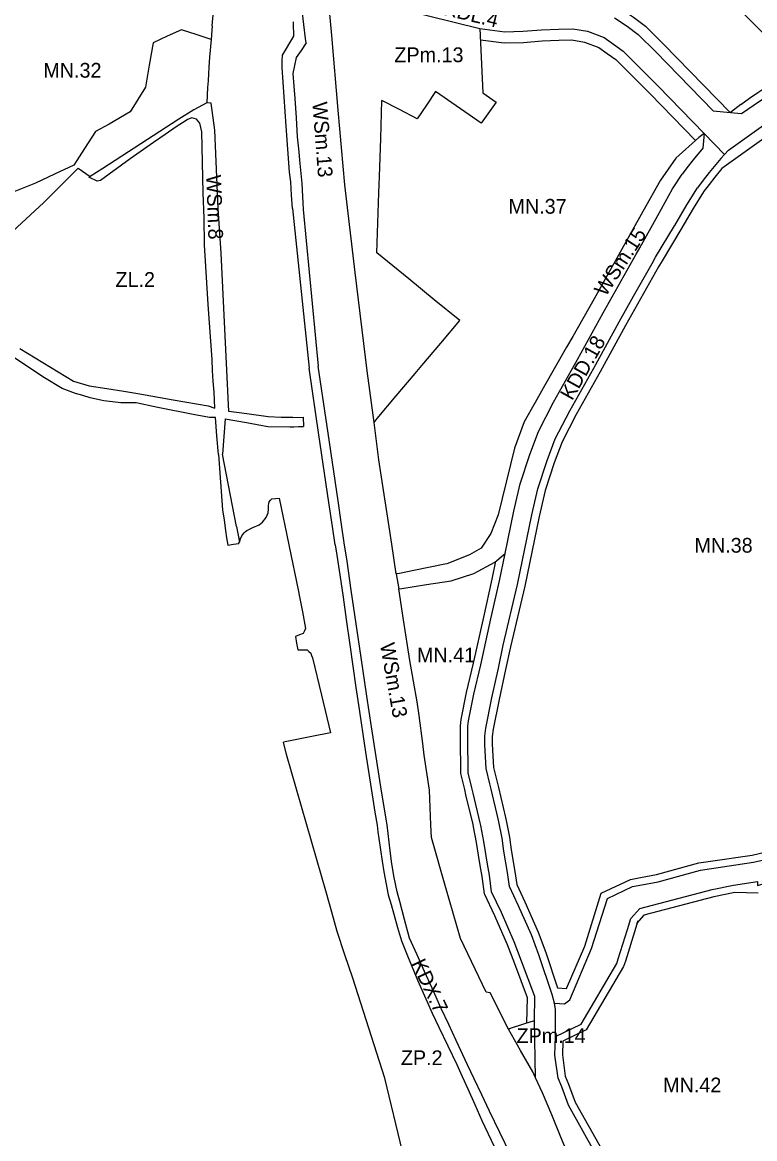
# Model space of a CAD drawing. Extents: x 7431080 to 7433370, y 5546450 to 5548428.
# Drawn here: x 7432562 to 7432959, y 5546903 to 5547508 of the extents above; entities that cross this region are included whole.
import ezdxf

# ---------------------------------------------------------------- set-up
doc = ezdxf.new("R2010")
doc.units = 0
for name, color, linetype in [('Linie Rozgraniczajace', 7, 'Continuous'), ('nieprzekraczalna linia zabudowy', 7, 'Continuous'), ('oznaczenia_przeznaczen', 7, 'Continuous')]:
    doc.layers.add(name, color=color, linetype=linetype)

msp = doc.modelspace()

# ---------------------------------------------------------------- linework, layer by layer
at = {"layer": 'Linie Rozgraniczajace'}
for p, q in [((7432665.2, 5547506.49), (7432664.53, 5547499.08)), ((7432709.13, 5547507.75), (7432709.11, 5547508.64)), ((7432709.31, 5547500.85), (7432709.13, 5547507.75)), ((7432883.07, 5547510.87), (7432889.86, 5547506.34)), ((7432889.86, 5547506.34), (7432895.91, 5547501.82)), ((7432895.91, 5547501.82), (7432905.46, 5547492.38)), ((7432592.52, 5547429.36), (7432599.07, 5547424.88)), ((7432708.89, 5547294.18), (7432714.49, 5547294.46)), ((7432714.49, 5547294.46), (7432714.64, 5547289.37)), ((7432822.84, 5547219.57), (7432823.82, 5547220.4)), ((7432764.79, 5547209.37), (7432766.17, 5547201.41))]:
    msp.add_line(p, q, dxfattribs=at)
for points in [[(7432684.27, 5547549.31), (7432684.63, 5547552.22), (7432685.71, 5547560.16), (7432692.57, 5547559.49), (7432702.74, 5547558.65), (7432706.07, 5547557.26), (7432714.86, 5547550.38), (7432718.05, 5547546.39), (7432720.97, 5547541.9), (7432726.36, 5547536.37), (7432730.08, 5547533.53), (7432738.98, 5547526.29), (7432754.14, 5547519.63), (7432768.49, 5547515.46), (7432810.21, 5547505.05)], [(7432665.2, 5547506.49), (7432665.75, 5547512.53), (7432667.77, 5547527.55), (7432669.79, 5547542.58)], [(7432774.33, 5547211.33), (7432766.65, 5547209.56), (7432764.79, 5547209.37), (7432762.43, 5547225.59), (7432755.48, 5547271.31), (7432752.81, 5547291.41), (7432749.09, 5547319.44), (7432742.62, 5547372.72), (7432736.91, 5547420.37), (7432733.47, 5547460.86), (7432730.03, 5547501.34), (7432727.43, 5547528.51), (7432726.36, 5547536.37)], [(7432928.37, 5547538.37), (7432936.78, 5547529.78), (7432945.54, 5547520.83), (7432954.3, 5547511.88), (7432958.8, 5547507.42), (7432963.3, 5547502.97), (7432972.96, 5547493.4), (7432982.62, 5547483.83)], [(7432716.06, 5547497.22), (7432715.66, 5547499.62), (7432714.76, 5547507.29), (7432713.86, 5547514.97)], [(7432640.78, 5547500.83), (7432633.11, 5547497.24), (7432631.07, 5547485.28), (7432629.04, 5547473.31), (7432624.91, 5547466.56), (7432620.78, 5547459.81), (7432609.32, 5547453.22), (7432601.93, 5547449.18), (7432596.03, 5547440.08), (7432590.13, 5547430.98), (7432579.76, 5547426.12), (7432569.39, 5547421.26), (7432543.12, 5547410.71), (7432516.84, 5547400.15), (7432508.77, 5547396.91), (7432500.7, 5547393.67), (7432500.07, 5547393.54), (7432492.82, 5547389.56), (7432485.57, 5547385.58), (7432484.07, 5547383.7), (7432482.57, 5547381.81)], [(7432664.53, 5547499.08), (7432656.52, 5547501.74), (7432648.45, 5547504.43), (7432640.78, 5547500.83)], [(7432708.67, 5547407.43), (7432708.19, 5547414.67), (7432707.71, 5547421.91), (7432707.05, 5547427.12), (7432706.17, 5547439.58), (7432705.29, 5547452.04), (7432704.14, 5547468), (7432702.99, 5547483.96), (7432703.12, 5547487.29), (7432703.24, 5547490.63), (7432709.31, 5547500.85)], [(7432810.21, 5547505.05), (7432811.69, 5547470.23), (7432818.94, 5547465.05), (7432810.8, 5547453.72), (7432786.16, 5547471.01)], [(7432810.21, 5547505.05), (7432823.61, 5547503.35), (7432833.51, 5547503.55)], [(7432833.51, 5547503.55), (7432843.54, 5547504.29), (7432852.74, 5547504.78), (7432860.43, 5547504.93), (7432868.49, 5547503.55), (7432877.4, 5547500.18), (7432882.61, 5547496.51), (7432887.79, 5547492.85), (7432897.26, 5547483.35), (7432906.72, 5547473.84), (7432931.58, 5547448.24), (7432942.68, 5547436.81)], [(7432664.53, 5547499.08), (7432663.67, 5547489.61), (7432663.35, 5547484.18), (7432663.13, 5547480.43), (7432662.92, 5547476.68), (7432662.57, 5547473.05), (7432662.28, 5547464.72)], [(7432716.06, 5547497.22), (7432713.27, 5547493.07), (7432710.71, 5547489.28), (7432709.78, 5547484.96), (7432708.85, 5547480.63), (7432709.41, 5547473.84), (7432709.96, 5547467.05), (7432710.59, 5547456.68), (7432711.22, 5547446.31), (7432712.03, 5547438.18), (7432712.49, 5547433.67), (7432713.75, 5547421.03), (7432714.11, 5547414.03), (7432714.29, 5547410.52)], [(7432905.46, 5547492.38), (7432936.53, 5547460.37), (7432945.96, 5547459.52), (7432951.94, 5547458.98)], [(7432951.44, 5547463.82), (7432956.27, 5547467.3), (7432960.65, 5547470.43), (7432962.98, 5547471.85), (7432972.8, 5547477.84), (7432982.62, 5547483.83)], [(7432786.16, 5547471.01), (7432781.15, 5547463.58), (7432776.15, 5547456.16), (7432766.64, 5547461.11), (7432757.13, 5547466.06)], [(7432708.89, 5547294.18), (7432704.88, 5547294.15), (7432702.53, 5547294.22), (7432695.5, 5547294.59), (7432683.88, 5547296.19), (7432674.21, 5547297.48), (7432670.08, 5547383.35), (7432668.43, 5547407.57), (7432666.58, 5547450), (7432664.66, 5547464.61), (7432662.41, 5547464.79), (7432662.28, 5547464.72), (7432655.28, 5547460.92), (7432647.01, 5547455.95), (7432605.86, 5547429.13), (7432599.07, 5547424.88), (7432598.33, 5547424.4)], [(7432752.81, 5547291.41), (7432754.6, 5547293.6), (7432764.87, 5547305.87), (7432775.14, 5547318.14), (7432778.69, 5547322.35), (7432788.98, 5547334.54), (7432799.27, 5547346.72), (7432785.46, 5547358.04), (7432771.65, 5547369.35), (7432762.95, 5547376.41), (7432754.25, 5547383.47), (7432754.85, 5547399.75), (7432755.45, 5547416.04), (7432755.6, 5547420.44), (7432755.75, 5547424.85), (7432756.44, 5547445.46), (7432757.13, 5547466.06)], [(7432951.44, 5547463.82), (7432945.96, 5547459.52)], [(7432951.94, 5547458.98), (7432958.79, 5547463.62), (7432965.39, 5547468.19)], [(7432560.85, 5547331.53), (7432585.82, 5547316.39), (7432590.09, 5547313.98), (7432598.54, 5547311.41), (7432608.02, 5547309.94), (7432617.34, 5547308.5), (7432624.88, 5547307.14), (7432644, 5547303.73), (7432663.03, 5547300.54), (7432666.51, 5547299.18), (7432666.19, 5547307.96), (7432665.72, 5547313.85), (7432665.25, 5547319.74), (7432665.05, 5547325.61), (7432663.03, 5547355.44), (7432661.04, 5547387.81), (7432660.75, 5547402.19), (7432660.18, 5547415.94), (7432659.57, 5547449.03), (7432658.53, 5547453.8), (7432656.7, 5547456.01), (7432654.09, 5547456.7), (7432651.79, 5547455.83), (7432650.95, 5547455.27), (7432645.71, 5547451.71), (7432639.73, 5547447.64), (7432633.41, 5547443.19), (7432620.69, 5547434.37)], [(7432944.76, 5547439.03), (7432965.08, 5547453.58), (7432971.88, 5547457.4)], [(7432931.58, 5547448.24), (7432928.7, 5547446.07), (7432916.31, 5547434.85), (7432908.06, 5547422.87), (7432898.49, 5547405.86), (7432872.15, 5547358.53), (7432860.44, 5547338.07)], [(7432931.58, 5547448.24), (7432931, 5547440.23), (7432925.7, 5547433.87), (7432922.36, 5547429.51), (7432919.79, 5547426.09)], [(7432620.69, 5547434.37), (7432604.64, 5547422.69), (7432602.9, 5547422.26), (7432598.33, 5547424.4)], [(7432944.76, 5547439.03), (7432942.68, 5547436.81), (7432940.62, 5547434.61), (7432934.3, 5547427), (7432931.12, 5547422.86), (7432927.99, 5547418.69)], [(7432592.52, 5547429.36), (7432583.24, 5547420.08), (7432573.95, 5547410.8), (7432528.05, 5547368.4), (7432529.17, 5547367.84), (7432530.29, 5547367.29), (7432525.74, 5547362.3), (7432521.19, 5547357.31)], [(7432820.79, 5547205.68), (7432823.82, 5547220.4), (7432828.6, 5547243.51), (7432831.96, 5547258.28), (7432837.16, 5547274.2), (7432841.86, 5547286.68), (7432850.06, 5547302.55), (7432863.11, 5547325.73), (7432876.88, 5547350.95), (7432894.75, 5547382.66), (7432896.75, 5547386.22), (7432906.53, 5547403.62), (7432914.57, 5547418.12), (7432919.79, 5547426.09)], [(7432830.58, 5547203.66), (7432838.37, 5547241.39), (7432841.61, 5547255.61), (7432846.6, 5547270.88), (7432851.01, 5547282.61), (7432858.86, 5547297.8), (7432871.86, 5547320.88), (7432885.62, 5547346.1), (7432893.47, 5547360.02), (7432903.46, 5547377.75), (7432905.39, 5547381.18), (7432915.61, 5547398.08), (7432915.65, 5547398.16), (7432915.7, 5547398.23), (7432922.34, 5547409.57), (7432927.99, 5547418.69)], [(7432714.29, 5547410.52), (7432714.47, 5547407.02), (7432722.59, 5547321.99)], [(7432708.67, 5547407.43), (7432717.66, 5547321.01)], [(7432663.63, 5547294.23), (7432654.79, 5547295.76), (7432635.74, 5547299.66), (7432623.93, 5547302.1), (7432615.72, 5547302.09), (7432611.11, 5547302.66), (7432606.5, 5547303.22), (7432598.99, 5547304.95), (7432595.07, 5547306.12), (7432591.15, 5547307.28), (7432583.92, 5547309.9), (7432574.27, 5547315.75), (7432553.87, 5547329.22), (7432541.98, 5547337.16), (7432533.37, 5547343.74), (7432530.34, 5547345.11)], [(7432860.44, 5547338.07), (7432857.12, 5547332.27), (7432844.46, 5547310.14), (7432840.05, 5547302.3), (7432834.15, 5547291.77), (7432828.9, 5547277.53), (7432820.11, 5547241.37), (7432816.15, 5547231.27), (7432810.77, 5547223.37), (7432804.57, 5547219.68), (7432792.19, 5547214.94), (7432791.24, 5547214.75), (7432774.33, 5547211.33)], [(7432731.77, 5547225.23), (7432730.29, 5547235.19), (7432728.38, 5547248.11), (7432723, 5547284.73), (7432717.66, 5547321.01)], [(7432736.7, 5547226.21), (7432735.22, 5547236.17), (7432733.31, 5547249.09), (7432727.92, 5547285.71), (7432722.59, 5547321.99)], [(7432668.54, 5547274.21), (7432667.74, 5547284.19), (7432666.93, 5547294.16), (7432663.63, 5547294.23)], [(7432672.22, 5547293.51), (7432671.44, 5547283.96), (7432670.66, 5547274.41)], [(7432672.22, 5547293.51), (7432683.76, 5547291.44), (7432695.29, 5547289.39), (7432707.2, 5547289.21), (7432709.29, 5547289.14)], [(7432709.29, 5547289.14), (7432711.96, 5547289.25), (7432714.64, 5547289.37)], [(7432668.54, 5547274.21), (7432669.64, 5547259.2), (7432670.74, 5547244.18), (7432671.54, 5547238.54), (7432672.35, 5547232.9), (7432672.96, 5547228.94), (7432673.58, 5547224.97), (7432676.61, 5547225.46), (7432679.64, 5547225.95), (7432679.61, 5547226.13), (7432679.86, 5547226.71), (7432680.54, 5547228.35), (7432681.23, 5547229.99), (7432681.82, 5547230.82), (7432682.41, 5547231.65), (7432683.12, 5547232.33), (7432683.84, 5547233.01), (7432687.21, 5547234.5), (7432690.57, 5547235.99), (7432692.46, 5547237.47), (7432694.38, 5547239.91), (7432694.95, 5547241.25), (7432695.52, 5547242.59), (7432695.62, 5547244.53), (7432695.72, 5547246.46), (7432695.9, 5547247.5), (7432696.07, 5547248.55), (7432696.74, 5547249.33), (7432697.4, 5547250.11), (7432699.45, 5547250.32), (7432701.5, 5547250.53), (7432706.71, 5547225.24), (7432711.92, 5547199.95), (7432712.34, 5547197.9), (7432714.02, 5547188.9), (7432715.7, 5547179.89), (7432715.11, 5547178.48), (7432714.51, 5547177.06), (7432712.37, 5547176.32), (7432710.23, 5547175.57), (7432710.84, 5547171.95), (7432711.45, 5547168.33), (7432714, 5547168.28), (7432716.54, 5547168.22), (7432717.53, 5547167.36), (7432718.52, 5547166.49), (7432719.01, 5547165.24), (7432719.5, 5547163.98), (7432724.33, 5547143.67), (7432729.17, 5547123.35), (7432719.19, 5547121.34), (7432709.21, 5547119.33), (7432706.53, 5547118.79), (7432703.85, 5547118.25)], [(7432678.25, 5547235.08), (7432670.66, 5547274.41)], [(7432678.25, 5547235.08), (7432679.86, 5547226.71)], [(7432731.77, 5547225.23), (7432732.65, 5547219.5), (7432734.25, 5547208.99), (7432736.02, 5547196.87), (7432737.78, 5547184.75), (7432739.74, 5547170.98), (7432743.03, 5547147.78), (7432744.35, 5547138.36), (7432748.23, 5547112.83), (7432752.1, 5547087.29), (7432753.28, 5547080.24), (7432754.46, 5547073.19), (7432754.96, 5547069.61), (7432755.46, 5547066.02), (7432756.3, 5547059.85), (7432757.15, 5547053.68), (7432758.21, 5547047.88), (7432760.52, 5547035.43), (7432762.01, 5547030.2), (7432763.5, 5547024.96), (7432765.57, 5547017.72), (7432767.63, 5547010.48), (7432770.96, 5547002.29), (7432776.51, 5546988.91), (7432781.54, 5546977.49), (7432784.35, 5546971.26), (7432787.92, 5546963.68), (7432797.66, 5546943.46), (7432800.62, 5546936.88), (7432803.59, 5546930.31), (7432807.44, 5546921.73), (7432811.29, 5546913.14), (7432817.81, 5546899.04)], [(7432826.52, 5546894.97), (7432820.99, 5546906.58), (7432815.45, 5546918.19), (7432811.29, 5546926.96), (7432807.13, 5546935.74), (7432805.32, 5546939.55), (7432803.51, 5546943.37), (7432797.38, 5546956.42), (7432793.32, 5546965.16), (7432789.26, 5546973.89), (7432784.3, 5546984.81), (7432780.24, 5546993.88), (7432776.18, 5547002.94), (7432772.03, 5547012.02), (7432769.38, 5547022), (7432766.72, 5547031.83), (7432765.31, 5547036.99), (7432763.79, 5547044.81), (7432762.53, 5547052.29), (7432761.5, 5547059.3), (7432759.88, 5547073.36), (7432756.92, 5547091.58), (7432751.47, 5547126.45), (7432748.99, 5547143.09), (7432745.81, 5547164.11), (7432740.4, 5547200.69), (7432738.17, 5547216.25), (7432736.7, 5547226.21)], [(7432825.66, 5546962.6), (7432815.82, 5546982.39), (7432813.5, 5546982.7), (7432799.7, 5547011.82), (7432791.79, 5547039.19), (7432783.87, 5547066.55), (7432783.51, 5547073.41), (7432782.8, 5547092.16), (7432780.05, 5547111.11), (7432779.23, 5547117.53), (7432777.33, 5547132.59), (7432776.17, 5547140.02), (7432772.2, 5547162.51), (7432768.79, 5547184.6), (7432766.17, 5547201.41), (7432767.88, 5547201.53), (7432781.25, 5547203.62), (7432794.63, 5547205.72), (7432806.96, 5547209.72), (7432818.23, 5547215.7), (7432822.84, 5547219.57)], [(7432803.65, 5547120.57), (7432803.7, 5547126.79), (7432804.01, 5547129.8), (7432806.9, 5547144.19), (7432810.6, 5547160.17), (7432816.11, 5547185.04), (7432820.79, 5547205.68)], [(7432812.8, 5547116.8), (7432812.88, 5547121.53), (7432813.42, 5547125.86), (7432816.69, 5547142.16), (7432820.17, 5547158.39), (7432822.85, 5547170.77), (7432830.58, 5547203.66)], [(7432859.46, 5546891.16), (7432854.03, 5546904.13), (7432849.08, 5546916.15), (7432844.16, 5546928.15), (7432840.27, 5546936.3), (7432839.67, 5546967.27), (7432839.96, 5546980.28), (7432832.77, 5546999.4), (7432828.8, 5547009.93), (7432821.85, 5547025.78), (7432816.52, 5547037.09), (7432815.32, 5547046.07), (7432814.29, 5547052.07), (7432813.33, 5547057.63), (7432812.35, 5547064.41), (7432810.66, 5547073.03), (7432810.38, 5547074.46), (7432806.52, 5547090.5), (7432805.88, 5547093.41), (7432803.86, 5547101.64), (7432803.65, 5547120.57)], [(7432765.1, 5546854.86), (7432771.53, 5546855.75), (7432777.96, 5546856.64), (7432773.13, 5546876.48), (7432768.29, 5546896.32), (7432758.63, 5546936), (7432749.94, 5546963.17), (7432741.24, 5546990.34), (7432737.04, 5547002.99), (7432732.83, 5547015.64), (7432729.94, 5547026.01), (7432727.04, 5547036.39), (7432716.21, 5547073.96), (7432705.39, 5547111.54), (7432703.85, 5547118.25)], [(7432873.16, 5546894.5), (7432858.21, 5546921.36), (7432854.53, 5546931.4), (7432852.51, 5546936.11), (7432850.82, 5546948.6), (7432851.19, 5546958.6), (7432851.1, 5546973.26), (7432850.53, 5546976.68), (7432849.29, 5546981.34), (7432842.13, 5547002.92), (7432838.06, 5547013.7), (7432830.95, 5547029.92), (7432826.23, 5547039.95), (7432825.21, 5547047.58), (7432823.21, 5547059.19), (7432822.21, 5547066.09), (7432820.47, 5547074.95), (7432820.15, 5547076.59), (7432816.27, 5547092.74), (7432815.62, 5547095.68), (7432813.6, 5547103.93), (7432812.8, 5547116.8)], [(7432850.53, 5546976.68), (7432855.97, 5546976.27), (7432858.91, 5546978.54), (7432870.7, 5547006.31), (7432879.21, 5547033.45), (7432892.92, 5547039.97), (7432897.83, 5547040.87), (7432906.82, 5547042.52), (7432929.63, 5547048.83), (7432935.6, 5547049.72), (7432958.38, 5547053.1), (7432978.31, 5547057.69), (7432984.23, 5547059.05), (7433001.64, 5547063.28)], [(7432891.92, 5547022.59), (7432896.75, 5547028.05), (7432936.06, 5547038.35), (7432947.55, 5547040.61), (7432960.49, 5547042.6), (7432960.58, 5547040.51), (7432998.53, 5547051.46), (7433013.49, 5547055.8)], [(7432851.19, 5546958.6), (7432864.95, 5546965.28), (7432884.34, 5546998.15), (7432885.15, 5547000.69), (7432890.11, 5547016.63), (7432891.92, 5547022.59)], [(7432825.66, 5546962.6), (7432826.29, 5546962.91), (7432834.54, 5546965.64), (7432839.67, 5546967.27)], [(7432840.27, 5546936.3), (7432838.81, 5546939.54), (7432832.14, 5546951.07), (7432825.66, 5546962.6)]]:
    msp.add_lwpolyline(points, dxfattribs=at)
at = {"layer": 'nieprzekraczalna linia zabudowy'}
for points in [[(7432830.08, 5547520.74), (7432836.46, 5547521.38), (7432844.98, 5547522.41), (7432852.04, 5547522.8), (7432861.36, 5547522.97), (7432865.02, 5547522.54), (7432866.6, 5547522.3), (7432869.63, 5547521.81), (7432872.05, 5547521.29), (7432875.09, 5547520.47), (7432879.22, 5547518.74), (7432881.83, 5547517.75), (7432885.83, 5547516.24), (7432893.32, 5547511.24), (7432899.83, 5547506.38), (7432909.72, 5547496.6)], [(7432810.47, 5547498.97), (7432823.29, 5547497.34), (7432833.79, 5547497.56)], [(7432833.79, 5547497.56), (7432843.92, 5547498.3), (7432852.95, 5547498.79), (7432859.97, 5547498.92), (7432866.91, 5547497.73), (7432874.57, 5547494.84), (7432879.15, 5547491.61), (7432883.9, 5547488.25), (7432902.45, 5547469.64), (7432926.9, 5547444.44)], [(7432909.72, 5547496.6), (7432945.69, 5547459.54)], [(7432967.71, 5547448.08), (7432941.31, 5547429.18)], [(7432941.31, 5547429.18), (7432937.43, 5547424.51), (7432934.31, 5547420.45), (7432931.19, 5547416.29)], [(7432931.39, 5547416.58), (7432925.77, 5547407.5), (7432919.06, 5547396.05), (7432919.05, 5547396.04), (7432908.85, 5547379.16), (7432906.95, 5547375.79), (7432889.12, 5547344.16), (7432875.35, 5547318.94), (7432862.38, 5547295.9), (7432854.67, 5547280.98), (7432850.38, 5547269.56), (7432845.47, 5547254.54), (7432842.28, 5547240.54), (7432834.49, 5547202.8)], [(7432835.64, 5546965.99), (7432835.94, 5546979.6), (7432829.03, 5546997.99), (7432825.09, 5547008.42), (7432818.21, 5547024.12), (7432812.64, 5547035.95), (7432811.37, 5547045.47), (7432810.35, 5547051.39), (7432809.38, 5547057), (7432808.41, 5547063.74), (7432806.73, 5547072.26), (7432806.47, 5547073.61), (7432802.62, 5547089.6), (7432801.98, 5547092.5), (7432799.87, 5547101.13), (7432799.65, 5547120.56), (7432799.7, 5547127.01), (7432800.05, 5547130.4), (7432802.99, 5547145.04), (7432806.7, 5547161.05), (7432812.21, 5547185.91), (7432816.88, 5547206.53), (7432818.88, 5547216.25)], [(7432834.49, 5547202.8), (7432826.75, 5547169.89), (7432824.08, 5547157.54), (7432820.6, 5547141.34), (7432817.37, 5547125.22), (7432816.88, 5547121.25), (7432816.8, 5547116.73)], [(7432816.79, 5547117.05), (7432817.57, 5547104.53), (7432819.52, 5547096.58), (7432820.16, 5547093.64), (7432824.06, 5547077.44), (7432824.4, 5547075.72), (7432826.16, 5547066.76), (7432827.16, 5547059.82), (7432829.16, 5547048.18), (7432830.11, 5547041.1), (7432834.6, 5547031.58), (7432841.77, 5547015.21), (7432845.9, 5547004.26), (7432852.29, 5546985)], [(7432852.29, 5546985), (7432857.14, 5546984.6), (7432866.94, 5547007.69), (7432875.92, 5547036.31), (7432891.68, 5547043.81), (7432897.11, 5547044.8), (7432905.92, 5547046.42), (7432928.8, 5547052.75), (7432935.01, 5547053.68), (7432957.64, 5547057.03), (7432977.41, 5547061.59), (7432983.31, 5547062.94), (7433000.7, 5547067.17)], [(7432960.85, 5547036.42), (7432948.24, 5547036.67), (7432936.95, 5547034.44), (7432898.94, 5547024.49), (7432894.92, 5547019.94)], [(7432895.75, 5547021.43), (7432893.93, 5547015.45), (7432888.97, 5546999.49), (7432888.01, 5546996.51), (7432867.78, 5546962.21), (7432855.1, 5546956.06)], [(7432855.1, 5546956.06), (7432854.83, 5546948.8), (7432856.4, 5546937.18), (7432858.25, 5546932.88), (7432861.86, 5546923.03), (7432876.16, 5546897.34), (7432885.09, 5546891.67), (7432898.03, 5546884.65), (7432907.34, 5546878.51), (7432915.05, 5546872.1), (7432923.32, 5546863.22), (7432930.66, 5546854.41), (7432932.33, 5546851.51), (7432934.33, 5546847.52), (7432936.49, 5546840.85), (7432937.58, 5546836.64), (7432940.35, 5546825.15)]]:
    msp.add_lwpolyline(points, dxfattribs=at)

# ---------------------------------------------------------------- texts
at = {"layer": 'oznaczenia_przeznaczen'}
for s, rotation, p in [('KDL.4', 346.29596, (7432790.17, 5547512.53)), ('WSm.13', 274.34981, (7432719.42, 5547465.02)), ('WSm.8', 271.96169, (7432661.9, 5547425.62)), ('WSm.15', 56.86691, (7432878.29, 5547359.32)), ('KDD.18', 60.67538, (7432860.19, 5547302.97)), ('WSm.13', 280.09114, (7432755.99, 5547171.29)), ('KDX.7', 295.2411, (7432772.81, 5546998.37))]:
    msp.add_text(s, height=8, rotation=rotation, dxfattribs=at).set_placement(p)
for s, p in [('ZPm.13', (7432763.83, 5547486.82)), ('MN.32', (7432573.65, 5547478.42)), ('MN.37', (7432825.66, 5547404.68)), ('ZL.2', (7432612.75, 5547365.01)), ('MN.38', (7432926.42, 5547220.93)), ('MN.41', (7432776.07, 5547161.45)), ('ZPm.14', (7432830.01, 5546955.1)), ('ZP.2', (7432767.35, 5546943.13)), ('MN.42', (7432909.46, 5546928.36))]:
    msp.add_text(s, height=8, dxfattribs=at).set_placement(p)

doc.saveas('drawing.dxf')
